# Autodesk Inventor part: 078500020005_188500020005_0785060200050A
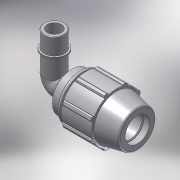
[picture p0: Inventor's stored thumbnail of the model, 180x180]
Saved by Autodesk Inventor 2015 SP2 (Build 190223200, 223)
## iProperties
Created: 2017-02
Part Number: 078500020005_188500020005_0785060200050A
Material: PVC-Piping
Description: PLASSON 90° ELBOW MALE ADAPTOR 20-1/2"
Document SubType Name: Modeling
Designer: KIM
Mass: 92.6774 g
Surface Area: 199.44 cm^2
Volume: 66.1981 cm^3
Density: 1.4 g/cm^3
Appearance: Smooth - White
Author: KIM
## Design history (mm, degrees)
derived "07850.ipt"
feature "Solid1::07850.ipt"
tag "TaggingFeature1"
body "Solid1"
other parameters: "d4" = 6.16667, "d5" = 18.5, "d7" = 48, "d9" = 10.57143, "d11" = 2.46667, "d13" = 120 deg, "d15" = 12 deg, "d16" = 41.76, "d18" = 1, "d19" = 35 deg, "d20" = 17.5 deg, "d21" = 44.64, "d23" = 0, "d25" = 360 deg, "d27" = 0.96, "d33" = 0.4, "d42" = 27.38, "d43" = 1.44, "d46" = 0.6, "d51" = 74, "d68" = 2.46667, "d72" = 41, "d73" = 20.955, "d74" = 17, "d75" = 24.09825, "d76" = 14.6685, "d77" = 18.7, "d79" = 8.382, "d80" = 0.62865, "d83" = 0, "d84" = 0, "d91" = 36, "d93" = 57, "d94" = 20.955, "d95" = 14.6685, "d96" = 7.4, "d97" = 50 deg, "E_" = 48, "A_" = 74, "l_" = 57, "l_2" = 17, "A_1" = 41, "R_" = 20.955
